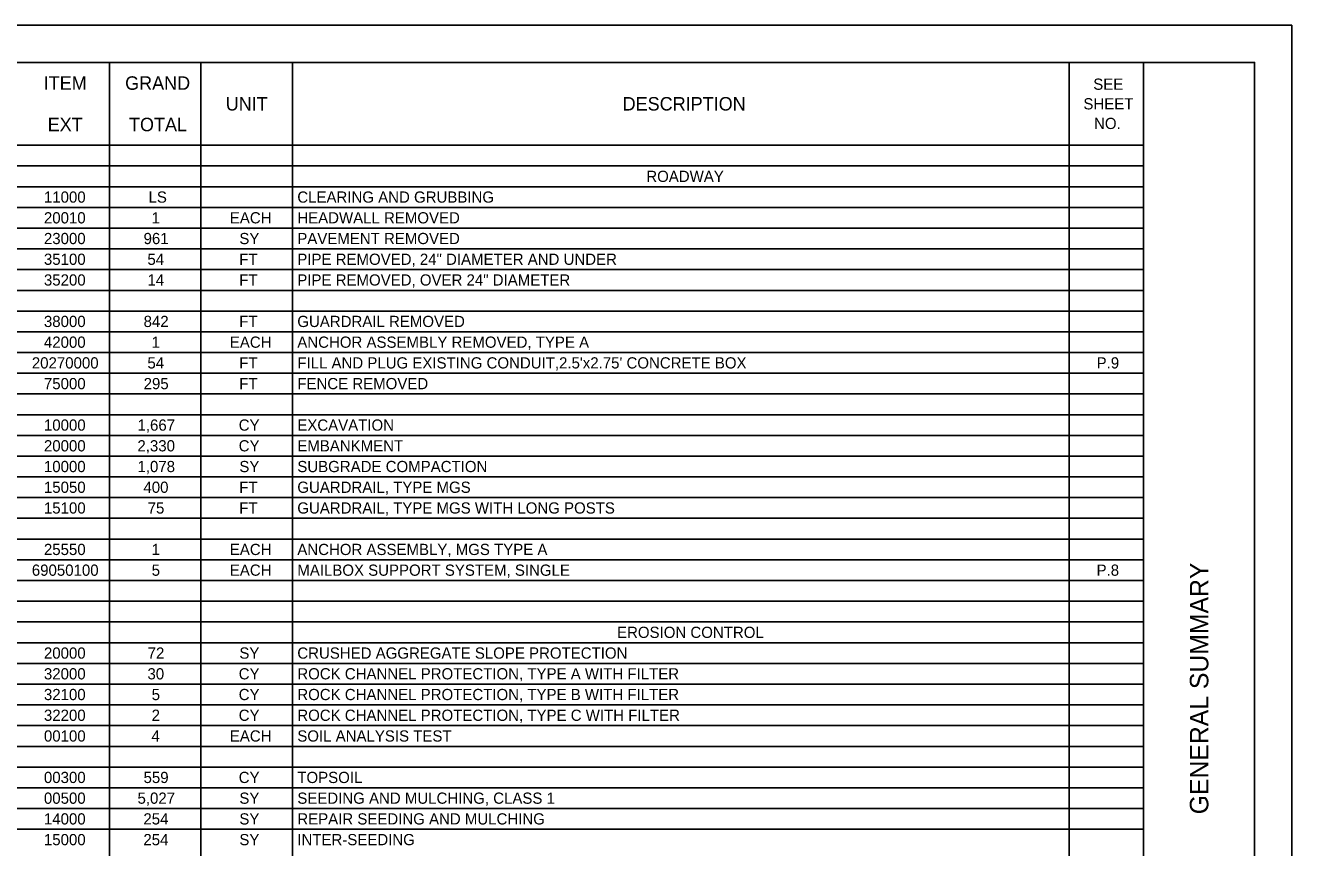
# Model space of a CAD drawing. Extents: x 0 to 1700, y 0 to 1100.
# Drawn here: x 845 to 1700, y 545 to 1100 of the extents above; entities that cross this region are included whole.
import ezdxf

# ---------------------------------------------------------------- set-up
doc = ezdxf.new("R2010")
doc.units = 0
for name, color, linetype in [('SH_Border', 7, 'Continuous'), ('SH_Cut_Line', 7, 'Continuous'), ('SH_Data', 7, 'Continuous'), ('SH_Text', 7, 'Continuous')]:
    doc.layers.add(name, color=color, linetype=linetype)

msp = doc.modelspace()

# ---------------------------------------------------------------- linework, layer by layer
at = {"layer": 'SH_Border'}
msp.add_line((1600, 25), (1600, 1075), dxfattribs=at)
msp.add_lwpolyline([(75, 1075), (1675, 1075), (1675, 25), (75, 25)], close=True, dxfattribs=at)
at = {"layer": 'SH_Cut_Line'}
msp.add_lwpolyline([(0, 0), (1700, 0), (1700, 1100), (0, 1100)], close=True, dxfattribs=at)
at = {"layer": 'SH_Text'}
for p, q in [((75, 1075), (1600, 1075)), ((901.73, 1075), (901.73, 25.12)), ((963.49, 1075), (963.49, 25.12)), ((1025.24, 1075), (1025.24, 25.12)), ((1549.77, 1075), (1549.77, 25.12)), ((1600, 1075), (1600, 25.12)), ((75, 1019.01), (1600, 1019.01)), ((75, 1005.01), (1600, 1005.01)), ((75, 991.01), (1600, 991.01)), ((75, 977.01), (1600, 977.01)), ((75, 963.01), (1600, 963.01)), ((75, 949.01), (1600, 949.01)), ((75, 935.02), (1600, 935.02)), ((75, 921.02), (1600, 921.02)), ((75, 907.02), (1600, 907.02)), ((75, 893.02), (1600, 893.02)), ((75, 879.02), (1600, 879.02)), ((75, 865.02), (1600, 865.02)), ((75, 851.03), (1600, 851.03)), ((75, 837.03), (1600, 837.03)), ((75, 823.03), (1600, 823.03)), ((75, 809.03), (1600, 809.03)), ((75, 795.03), (1600, 795.03)), ((75, 781.03), (1600, 781.03)), ((75, 767.04), (1600, 767.04)), ((75, 753.04), (1600, 753.04)), ((75, 739.04), (1600, 739.04)), ((75, 725.04), (1600, 725.04)), ((75, 711.04), (1600, 711.04)), ((75, 697.04), (1600, 697.04)), ((75, 683.05), (1600, 683.05)), ((75, 669.05), (1600, 669.05)), ((75, 655.05), (1600, 655.05)), ((75, 641.05), (1600, 641.05)), ((75, 627.05), (1600, 627.05)), ((75, 613.05), (1600, 613.05)), ((75, 599.06), (1600, 599.06)), ((75, 585.06), (1600, 585.06)), ((75, 571.06), (1600, 571.06)), ((75, 557.06), (1600, 557.06))]:
    msp.add_line(p, q, dxfattribs=at)

# ---------------------------------------------------------------- texts
at = {"layer": 'SH_Data'}
msp.add_text('GENERAL SUMMARY', height=12.5, rotation=90, dxfattribs=at).set_placement((1643.75, 567.18))
at = {"layer": 'SH_Text'}
for s, height, p in [('ITEM', 9.091, (857.27, 1056.46)), ('GRAND', 9.091, (912.27, 1056.46)), ('SEE ', 7.576, (1566.01, 1056.47)), ('UNIT', 9.091, (980.2, 1042.46)), ('DESCRIPTION', 9.0907, (1248.23, 1042.46)), ('SHEET ', 7.576, (1559.34, 1043.22)), ('EXT', 9.091, (859.97, 1028.46)), ('TOTAL', 9.091, (914.86, 1028.46)), ('NO.', 7.576, (1566.56, 1029.96)), ('ROADWAY', 7.576, (1264.2, 994.22)), ('11000', 7.576, (857.43, 980.22)), ('LS', 7.576, (928.08, 980.22)), ('CLEARING AND GRUBBING', 7.5756, (1028.54, 980.22)), ('20010', 7.576, (857.43, 966.22)), ('1', 7.58, (930.18, 966.22)), ('EACH', 7.576, (982.97, 966.22)), ('HEADWALL REMOVED', 7.5756, (1028.54, 966.22)), ('23000', 7.576, (857.43, 952.23)), ('961', 7.576, (924.74, 952.23)), ('SY', 7.576, (989.41, 952.23)), ('PAVEMENT REMOVED', 7.5756, (1028.54, 952.23)), ('35100', 7.576, (857.43, 938.23)), ('54', 7.576, (927.32, 938.23)), ('FT', 7.576, (989.32, 938.23)), ('PIPE REMOVED, 24" DIAMETER AND UNDER', 7.5756, (1028.54, 938.23)), ('35200', 7.576, (857.43, 924.23)), ('14', 7.576, (927.32, 924.23)), ('FT', 7.576, (989.32, 924.23)), ('PIPE REMOVED, OVER 24" DIAMETER', 7.5756, (1028.54, 924.23)), ('38000', 7.576, (857.43, 896.23)), ('842', 7.576, (924.74, 896.23)), ('FT', 7.576, (989.32, 896.23)), ('GUARDRAIL REMOVED', 7.5756, (1028.54, 896.23)), ('42000', 7.576, (857.43, 882.23)), ('1', 7.58, (930.18, 882.23)), ('EACH', 7.576, (982.97, 882.23)), ('ANCHOR ASSEMBLY REMOVED, TYPE A', 7.5756, (1028.54, 882.23)), ('20270000', 7.576, (849.27, 868.24)), ('54', 7.576, (927.32, 868.24)), ('FT', 7.576, (989.32, 868.24)), ("FILL AND PLUG EXISTING CONDUIT,2.5'x2.75' CONCRETE BOX", 7.5756, (1028.54, 868.24)), ('P.9', 7.576, (1568.3, 868.24)), ('75000', 7.576, (857.43, 854.24)), ('295', 7.576, (924.76, 854.24)), ('FT', 7.576, (989.32, 854.24)), ('FENCE REMOVED', 7.5756, (1028.54, 854.24)), ('10000', 7.576, (857.43, 826.24)), ('1,667', 7.576, (920.63, 826.24)), ('CY', 7.576, (988.96, 826.24)), ('EXCAVATION', 7.576, (1028.54, 826.24)), ('20000', 7.576, (857.43, 812.24)), ('2,330', 7.576, (920.57, 812.24)), ('CY', 7.576, (988.96, 812.24)), ('EMBANKMENT', 7.576, (1028.54, 812.24)), ('10000', 7.576, (857.43, 798.24)), ('1,078', 7.576, (920.6, 798.24)), ('SY', 7.576, (989.41, 798.24)), ('SUBGRADE COMPACTION', 7.5756, (1028.54, 798.24)), ('15050', 7.576, (857.43, 784.25)), ('400', 7.576, (924.63, 784.25)), ('FT', 7.576, (989.32, 784.25)), ('GUARDRAIL, TYPE MGS', 7.5756, (1028.54, 784.25)), ('15100', 7.576, (857.43, 770.25)), ('75', 7.576, (927.48, 770.25)), ('FT', 7.576, (989.32, 770.25)), ('GUARDRAIL, TYPE MGS WITH LONG POSTS', 7.5756, (1028.54, 770.25)), ('25550', 7.576, (857.43, 742.25)), ('1', 7.58, (930.18, 742.25)), ('EACH', 7.576, (982.97, 742.25)), ('ANCHOR ASSEMBLY, MGS TYPE A', 7.5756, (1028.54, 742.25)), ('69050100', 7.576, (849.27, 728.25)), ('5', 7.58, (930.2, 728.25)), ('EACH', 7.576, (982.97, 728.25)), ('MAILBOX SUPPORT SYSTEM, SINGLE', 7.5756, (1028.54, 728.25)), ('P.8', 7.576, (1568.25, 728.25)), ('EROSION CONTROL', 7.5756, (1244.45, 686.26)), ('20000', 7.576, (857.43, 672.26)), ('72', 7.576, (927.46, 672.26)), ('SY', 7.576, (989.41, 672.26)), ('CRUSHED AGGREGATE SLOPE PROTECTION', 7.5756, (1028.54, 672.26)), ('32000', 7.576, (857.43, 658.26)), ('30', 7.576, (927.35, 658.26)), ('CY', 7.576, (988.96, 658.26)), ('ROCK CHANNEL PROTECTION, TYPE A WITH FILTER', 7.5756, (1028.54, 658.26)), ('32100', 7.576, (857.43, 644.26)), ('5', 7.58, (930.2, 644.26)), ('CY', 7.576, (988.96, 644.26)), ('ROCK CHANNEL PROTECTION, TYPE B WITH FILTER', 7.5756, (1028.54, 644.26)), ('32200', 7.576, (857.43, 630.26)), ('2', 7.58, (930.18, 630.26)), ('CY', 7.576, (988.96, 630.26)), ('ROCK CHANNEL PROTECTION, TYPE C WITH FILTER', 7.5756, (1028.54, 630.26)), ('00100', 7.576, (857.43, 616.26)), ('4', 7.58, (930.04, 616.26)), ('EACH', 7.576, (982.97, 616.26)), ('SOIL ANALYSIS TEST', 7.5756, (1028.54, 616.26)), ('00300', 7.576, (857.43, 588.27)), ('559', 7.576, (924.72, 588.27)), ('CY', 7.576, (988.96, 588.27)), ('TOPSOIL', 7.576, (1028.54, 588.27)), ('00500', 7.576, (857.43, 574.27)), ('5,027', 7.576, (920.63, 574.27)), ('SY', 7.576, (989.41, 574.27)), ('SEEDING AND MULCHING, CLASS 1', 7.5756, (1028.54, 574.27)), ('14000', 7.576, (857.43, 560.27)), ('254', 7.576, (924.6, 560.27)), ('SY', 7.576, (989.41, 560.27)), ('REPAIR SEEDING AND MULCHING', 7.5756, (1028.54, 560.27)), ('15000', 7.576, (857.43, 546.27)), ('254', 7.576, (924.6, 546.27)), ('SY', 7.576, (989.41, 546.27)), ('INTER-SEEDING', 7.5756, (1028.54, 546.27))]:
    msp.add_text(s, height=height, dxfattribs=at).set_placement(p)

doc.saveas('drawing.dxf')
